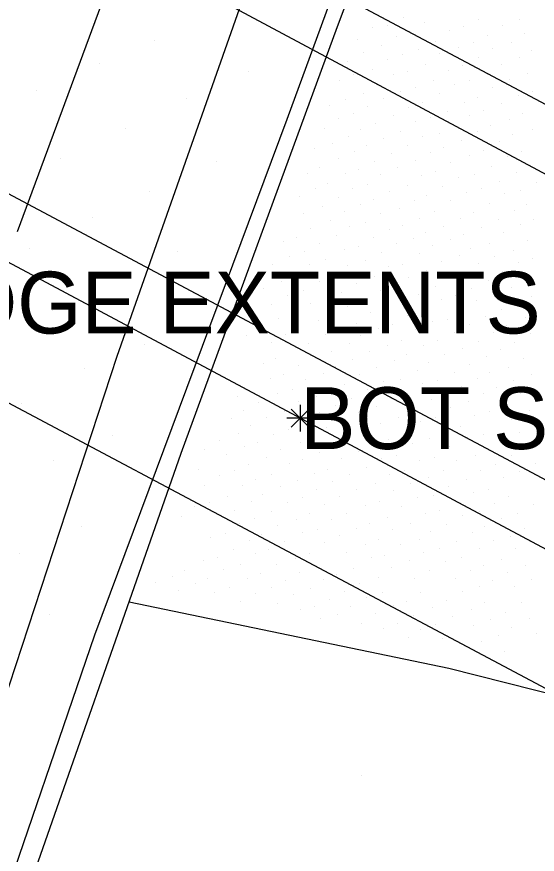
# Model space of a CAD drawing. Extents: x 1729983 to 1730242, y 468641 to 469019.
# Drawn here: x 1730109.61 to 1730124.77, y 468724.33 to 468748.72 of the extents above; entities that cross this region are included whole.
import ezdxf

# ---------------------------------------------------------------- set-up
doc = ezdxf.new("R2010")
doc.units = 0
for name, color, linetype in [('Default', 7, 'Continuous'), ('S_Curb_Type_1', 7, 'Continuous'), ('S_Ground_SpotElevation', 7, 'Continuous'), ('S_Misc_MiscFeature', 7, 'Continuous'), ('S_Misc_MiscItems', 7, 'Continuous'), ('S_Roadway_Edge_Pavement', 7, 'Continuous'), ('S_Roadway_Painted_Lines', 7, 'Continuous'), ('S_Roadway_Sidewalks', 7, 'Continuous'), ('S_Text', 7, 'Continuous')]:
    doc.layers.add(name, color=color, linetype=linetype)

# ---------------------------------------------------------------- blocks, each defined once
blk = doc.blocks.new('POINT_DISPLAY')
at = {"layer": 'Default'}
blk.add_line((0, 0), (0, 0), dxfattribs=at)

msp = doc.modelspace()

# ---------------------------------------------------------------- linework, layer by layer
at = {"layer": 'S_Curb_Type_1'}
msp.add_lwpolyline([(1730095.691, 468641.415), (1730095.909, 468646.136), (1730096.354, 468653.521), (1730096.818, 468653.995), (1730097.198, 468655.848), (1730096.66, 468657.036), (1730097.062, 468660.797), (1730098.243, 468671.757), (1730099.533, 468680.946), (1730101.556, 468692.14), (1730103.524, 468700.629), (1730106.497, 468712.327), (1730109.421, 468721.771), (1730114.404, 468736.003), (1730118.96, 468748.434), (1730124.347, 468762.755), (1730131.22, 468781.92), (1730136.349, 468795.804), (1730142.854, 468813.477), (1730149.849, 468832.496), (1730156.774, 468851.574), (1730163.434, 468869.402), (1730166.697, 468878.04), (1730172.479, 468894.171)], dxfattribs=at)
at = {"layer": 'S_Misc_MiscFeature'}
for p, q in [((1730119.737, 468769.782), (1730109.624, 468742.454)), ((1730134.131, 468741.31), (1730106.222, 468756.158)), ((1730105.571, 468754.535), (1730133.572, 468739.555)), ((1730102.847, 468747.037), (1730130.837, 468732.131)), ((1730130.252, 468730.415), (1730102.19, 468745.399)), ((1730130.021, 468726.489), (1730100.897, 468741.974))]:
    msp.add_line(p, q, dxfattribs=at)
at = {"layer": 'S_Misc_MiscItems'}
for p, q in [((1730118.134, 468736.763), (1730117.61, 468737.287)), ((1730118.134, 468737.287), (1730117.61, 468736.763)), ((1730117.872, 468737.418), (1730117.872, 468736.632)), ((1730118.265, 468737.025), (1730117.479, 468737.025))]:
    msp.add_line(p, q, dxfattribs=at)
at = {"layer": 'S_Roadway_Edge_Pavement'}
msp.add_lwpolyline([(1730169.443, 468886.971), (1730164.503, 468873.715), (1730156.499, 468852.01), (1730147.717, 468828.276), (1730138.371, 468802.607), (1730128.942, 468777.012), (1730117.481, 468745.727), (1730111.874, 468730.709), (1730108.888, 468721.988), (1730105.794, 468711.827), (1730102.94, 468700.647), (1730101.123, 468692.177), (1730099.16, 468681.419), (1730097.818, 468671.805), (1730096.586, 468660.812), (1730096.168, 468657.103), (1730095.956, 468653.708), (1730095.867, 468652.572), (1730095.424, 468646.027), (1730095.252, 468641.367)], dxfattribs=at)
at = {"layer": 'S_Roadway_Painted_Lines'}
msp.add_lwpolyline([(1730094.799, 468656.256), (1730095.17, 468660.96), (1730096.083, 468669.985), (1730097.638, 468680.767), (1730099.581, 468691.95), (1730101.134, 468699.687), (1730104.772, 468714.073), (1730108.651, 468727.01), (1730112.542, 468738.83), (1730119.789, 468759.429), (1730137.203, 468807.807), (1730148.896, 468839.717), (1730160.486, 468871.271), (1730175.799, 468912.851), (1730190.41, 468952.883), (1730200.037, 468978.351)], dxfattribs=at)
at = {"layer": 'S_Roadway_Sidewalks'}
msp.add_lwpolyline([(1730127.192, 468728.47), (1730122.195, 468729.739), (1730112.887, 468731.671)], dxfattribs=at)

# ---------------------------------------------------------------- block references
at = {"layer": 'S_Ground_SpotElevation'}
for p in [(1730120.885, 468748.692), (1730120.425, 468748.456), (1730121.491, 468748.549), (1730123.059, 468748.64), (1730123.749, 468748.457), (1730124.269, 468748.622), (1730119.966, 468748.396), (1730121.041, 468748.291), (1730122.22, 468748.316), (1730122.635, 468748.418), (1730124.412, 468748.23), (1730113.631, 468748.018), (1730119.547, 468748.059), (1730120.686, 468748.132), (1730121.802, 468748.003), (1730122.925, 468747.955), (1730123.33, 468748.178), (1730124.011, 468747.965), (1730120.247, 468747.874), (1730121.304, 468747.768), (1730122.482, 468747.815), (1730123.484, 468747.8), (1730124.608, 468747.73), (1730119.71, 468747.688), (1730120.4, 468747.468), (1730120.854, 468747.612), (1730121.938, 468747.652), (1730123.058, 468747.522), (1730124.25, 468747.515), (1730112.022, 468747.363), (1730119.245, 468747.42), (1730121.517, 468747.33), (1730122.582, 468747.296), (1730123.736, 468747.321), (1730116.352, 468747.126), (1730119.413, 468747.032), (1730119.974, 468747.18), (1730120.576, 468747.028), (1730121.002, 468747.118), (1730122.2, 468747.144), (1730123.317, 468747.027), (1730124.485, 468747.076), (1730119.021, 468746.87), (1730120.131, 468746.767), (1730121.757, 468746.855), (1730122.365, 468746.743), (1730122.808, 468746.858), (1730123.962, 468746.882), (1730110.192, 468746.566), (1730119.71, 468746.489), (1730120.805, 468746.543), (1730121.218, 468746.669), (1730123.479, 468746.648), (1730124.635, 468746.537), (1730114.56, 468746.334), (1730119.178, 468746.303), (1730120.301, 468746.333), (1730121.917, 468746.466), (1730123.031, 468746.367), (1730124.217, 468746.41), (1730118.73, 468746.12), (1730119.834, 468746.11), (1730121.03, 468746.081), (1730121.442, 468746.211), (1730122.648, 468746.21), (1730123.733, 468746.178), (1730119.435, 468745.911), (1730120.574, 468745.832), (1730121.65, 468745.77), (1730122.171, 468745.966), (1730122.794, 468745.841), (1730123.194, 468745.989), (1730124.357, 468745.896), (1730118.986, 468745.753), (1730120.063, 468745.621), (1730121.229, 468745.656), (1730122.333, 468745.576), (1730123.42, 468745.554), (1730123.978, 468745.728), (1730112.782, 468745.464), (1730118.587, 468745.467), (1730119.611, 468745.427), (1730120.802, 468745.362), (1730121.917, 468745.327), (1730123.036, 468745.381), (1730124.048, 468745.273), (1730124.647, 468745.446), (1730119.267, 468745.223), (1730120.305, 468745.166), (1730121.439, 468745.225), (1730122.57, 468745.11), (1730123.68, 468745.079), (1730118.283, 468744.88), (1730118.817, 468745.015), (1730119.465, 468744.785), (1730119.809, 468744.97), (1730120.995, 468744.953), (1730122.047, 468744.913), (1730123.206, 468744.814), (1730124.32, 468744.784), (1730110.88, 468744.576), (1730118.997, 468744.6), (1730120.518, 468744.724), (1730121.222, 468744.543), (1730121.677, 468744.755), (1730122.8, 468744.666), (1730123.918, 468744.633), (1730115.439, 468744.51), (1730118.43, 468744.325), (1730120.027, 468744.51), (1730120.696, 468744.339), (1730122.259, 468744.479), (1730123.455, 468744.357), (1730124.491, 468744.397), (1730118.095, 468744.162), (1730119.201, 468744.143), (1730119.562, 468744.281), (1730120.219, 468744.111), (1730121.391, 468744.078), (1730121.805, 468744.22), (1730122.937, 468744.131), (1730124.168, 468744.168), (1730118.65, 468743.868), (1730119.821, 468743.835), (1730120.994, 468743.811), (1730122.489, 468744.031), (1730123.677, 468743.932), (1730124.739, 468743.901), (1730113.481, 468743.638), (1730118.317, 468743.712), (1730119.4, 468743.702), (1730120.481, 468743.633), (1730122.02, 468743.783), (1730122.71, 468743.605), (1730123.151, 468743.715), (1730123.826, 468743.572), (1730124.288, 468743.642), (1730117.849, 468743.494), (1730118.987, 468743.438), (1730120.003, 468743.382), (1730121.206, 468743.375), (1730121.552, 468743.524), (1730122.233, 468743.355), (1730118.518, 468743.189), (1730119.638, 468743.25), (1730120.769, 468743.126), (1730123.374, 468743.283), (1730124.466, 468743.245), (1730111.818, 468742.883), (1730117.966, 468742.996), (1730119.148, 468743.058), (1730120.218, 468742.991), (1730121.331, 468742.844), (1730121.767, 468743.057), (1730122.532, 468742.849), (1730122.918, 468743.008), (1730124.101, 468743.063), (1730118.753, 468742.77), (1730119.297, 468742.594), (1730119.767, 468742.737), (1730120.859, 468742.642), (1730122.053, 468742.604), (1730123.631, 468742.805), (1730124.281, 468742.652), (1730124.66, 468742.818), (1730118.173, 468742.557), (1730118.929, 468742.354), (1730120.483, 468742.511), (1730121.519, 468742.443), (1730122.629, 468742.373), (1730123.141, 468742.576), (1730123.798, 468742.418), (1730117.372, 468742.16), (1730117.767, 468742.291), (1730118.429, 468742.12), (1730119.996, 468742.3), (1730120.671, 468742.105), (1730121.183, 468742.263), (1730122.233, 468742.238), (1730123.381, 468742.121), (1730124.481, 468742.212), (1730109.989, 468741.962), (1730114.295, 468741.886), (1730118.005, 468741.867), (1730119.147, 468741.924), (1730119.56, 468742.035), (1730121.716, 468742.046), (1730122.834, 468741.971), (1730124.075, 468741.904), (1730117.556, 468741.747), (1730118.592, 468741.634), (1730119.778, 468741.612), (1730120.249, 468741.836), (1730121.334, 468741.814), (1730122.521, 468741.75), (1730123.534, 468741.745), (1730124.623, 468741.689), (1730117.069, 468741.5), (1730118.132, 468741.508), (1730119.245, 468741.463), (1730120.431, 468741.43), (1730120.853, 468741.51), (1730121.993, 468741.577), (1730123.076, 468741.515), (1730124.223, 468741.547), (1730112.474, 468741.147), (1730117.771, 468741.28), (1730118.835, 468741.146), (1730120.028, 468741.139), (1730121.024, 468741.131), (1730121.538, 468741.313), (1730122.175, 468741.168), (1730122.628, 468741.261), (1730123.768, 468741.302), (1730117.321, 468741.016), (1730118.432, 468741.017), (1730119.513, 468740.948), (1730120.558, 468740.904), (1730123.341, 468741.021), (1730124.455, 468740.972), (1730116.808, 468740.793), (1730117.969, 468740.744), (1730119.061, 468740.689), (1730120.198, 468740.744), (1730121.304, 468740.638), (1730121.801, 468740.853), (1730122.87, 468740.803), (1730123.486, 468740.66), (1730124.02, 468740.832), (1730117.506, 468740.596), (1730119.762, 468740.47), (1730120.839, 468740.391), (1730121.982, 468740.475), (1730122.38, 468740.594), (1730123.014, 468740.447), (1730124.61, 468740.567), (1730110.657, 468740.17), (1730117.039, 468740.344), (1730118.164, 468740.359), (1730119.256, 468740.279), (1730120.318, 468740.212), (1730121.549, 468740.204), (1730122.586, 468740.185), (1730123.745, 468740.184), (1730124.17, 468740.293), (1730117.228, 468739.927), (1730117.723, 468740.117), (1730118.807, 468740.024), (1730119.913, 468740.098), (1730121.005, 468740.018), (1730122.156, 468739.912), (1730123.259, 468739.975), (1730124.437, 468739.957), (1730118.392, 468739.881), (1730119.504, 468739.793), (1730120.56, 468739.749), (1730121.716, 468739.833), (1730122.81, 468739.745), (1730123.891, 468739.713), (1730116.296, 468739.431), (1730116.768, 468739.658), (1730117.438, 468739.457), (1730118.592, 468739.452), (1730119.017, 468739.579), (1730119.638, 468739.436), (1730120.153, 468739.629), (1730121.232, 468739.595), (1730122.352, 468739.511), (1730123.5, 468739.521), (1730124.57, 468739.478), (1730117.023, 468739.243), (1730118.117, 468739.197), (1730119.297, 468739.207), (1730120.81, 468739.286), (1730121.857, 468739.298), (1730123.054, 468739.268), (1730124.113, 468739.228), (1730113.344, 468739.168), (1730118.791, 468738.963), (1730119.879, 468738.957), (1730120.409, 468739.14), (1730121.473, 468739.153), (1730122.584, 468739.048), (1730123.708, 468739.026), (1730117.164, 468738.775), (1730118.304, 468738.788), (1730119.39, 468738.736), (1730120.628, 468738.71), (1730120.97, 468738.88), (1730122.06, 468738.878), (1730123.294, 468738.811), (1730124.361, 468738.766), (1730111.588, 468738.464), (1730116.797, 468738.63), (1730117.814, 468738.57), (1730118.908, 468738.525), (1730120.102, 468738.508), (1730121.596, 468738.638), (1730122.805, 468738.598), (1730123.926, 468738.501), (1730117.395, 468738.296), (1730118.552, 468738.338), (1730119.588, 468738.287), (1730121.275, 468738.411), (1730122.362, 468738.344), (1730123.373, 468738.35), (1730124.614, 468738.306), (1730117.004, 468738.188), (1730118.031, 468738.165), (1730119.171, 468738.019), (1730120.307, 468738.089), (1730120.786, 468738.162), (1730121.43, 468738.047), (1730121.873, 468738.135), (1730123.019, 468738.167), (1730124.096, 468738.119), (1730117.209, 468737.736), (1730117.654, 468737.866), (1730118.802, 468737.881), (1730119.815, 468737.862), (1730120.988, 468737.755), (1730122.067, 468737.713), (1730122.554, 468737.933), (1730123.207, 468737.732), (1730123.592, 468737.921), (1730124.288, 468737.732), (1730116.042, 468737.652), (1730116.653, 468737.469), (1730117.823, 468737.509), (1730118.352, 468737.646), (1730119.373, 468737.599), (1730120.511, 468737.603), (1730121.682, 468737.575), (1730122.762, 468737.504), (1730109.763, 468737.462), (1730116.212, 468737.255), (1730118.9, 468737.391), (1730120.09, 468737.378), (1730121.236, 468737.285), (1730122.239, 468737.327), (1730123.909, 468737.398), (1730124.542, 468737.252), (1730115.859, 468737.003), (1730116.897, 468737.04), (1730117.423, 468737.217), (1730118.437, 468737.18), (1730119.563, 468737.201), (1730120.737, 468737.053), (1730121.796, 468737.045), (1730122.945, 468737.112), (1730123.372, 468737.218), (1730124.034, 468736.982), (1730116.409, 468736.819), (1730118.002, 468736.941), (1730118.644, 468736.751), (1730119.102, 468736.971), (1730120.204, 468736.872), (1730121.366, 468736.942), (1730122.548, 468736.779), (1730112.399, 468736.518), (1730116.081, 468736.589), (1730117.098, 468736.564), (1730117.534, 468736.708), (1730119.329, 468736.51), (1730119.869, 468736.666), (1730120.967, 468736.603), (1730122.052, 468736.606), (1730123.208, 468736.562), (1730124.256, 468736.615), (1730115.531, 468736.382), (1730116.618, 468736.321), (1730117.865, 468736.309), (1730118.274, 468736.473), (1730120.437, 468736.416), (1730121.154, 468736.275), (1730121.639, 468736.437), (1730122.697, 468736.432), (1730123.861, 468736.387), (1730115.077, 468736.125), (1730116.253, 468736.197), (1730117.284, 468736.102), (1730118.426, 468736.013), (1730118.917, 468736.218), (1730119.558, 468736.049), (1730120.054, 468736.24), (1730122.208, 468736.199), (1730123.351, 468736.103), (1730124.494, 468736.165), (1730110.691, 468735.789), (1730115.717, 468735.969), (1730116.881, 468735.87), (1730117.932, 468735.825), (1730119.067, 468735.84), (1730120.236, 468735.855), (1730120.676, 468735.951), (1730121.351, 468735.778), (1730121.786, 468735.892), (1730122.428, 468735.782), (1730122.977, 468735.936), (1730124.011, 468735.925), (1730114.919, 468735.522), (1730116.37, 468735.664), (1730117.557, 468735.693), (1730118.659, 468735.541), (1730119.798, 468735.585), (1730123.55, 468735.688), (1730124.734, 468735.704), (1730115.515, 468735.349), (1730115.968, 468735.496), (1730117.043, 468735.389), (1730118.274, 468735.417), (1730119.303, 468735.37), (1730120.474, 468735.394), (1730120.903, 468735.501), (1730121.599, 468735.31), (1730122.051, 468735.489), (1730123.113, 468735.511), (1730123.802, 468735.297), (1730124.243, 468735.468), (1730115.095, 468735.073), (1730116.192, 468735.064), (1730116.568, 468735.236), (1730117.283, 468735.025), (1730117.795, 468735.206), (1730118.799, 468735.181), (1730120.05, 468735.11), (1730121.085, 468735.116), (1730122.193, 468735.042), (1730122.727, 468735.248), (1730116.767, 468734.806), (1730118.338, 468734.952), (1730119.52, 468734.944), (1730120.579, 468734.907), (1730122.905, 468734.852), (1730123.343, 468734.953), (1730115.215, 468734.569), (1730115.741, 468734.756), (1730116.447, 468734.585), (1730117.504, 468734.568), (1730117.95, 468734.703), (1730119.023, 468734.737), (1730120.175, 468734.598), (1730121.277, 468734.702), (1730121.744, 468734.769), (1730122.456, 468734.565), (1730123.528, 468734.54), (1730123.943, 468734.73), (1730114.788, 468734.454), (1730115.962, 468734.327), (1730117.041, 468734.307), (1730118.565, 468734.501), (1730119.765, 468734.475), (1730120.826, 468734.442), (1730121.921, 468734.348), (1730123.091, 468734.294), (1730124.659, 468734.501), (1730114.424, 468734.175), (1730115.491, 468734.22), (1730116.527, 468734.1), (1730117.752, 468734.077), (1730118.132, 468734.236), (1730118.774, 468734.078), (1730119.214, 468734.261), (1730120.408, 468734.145), (1730121.522, 468734.24), (1730122.606, 468734.2), (1730123.73, 468734.112), (1730124.199, 468734.263), (1730111.513, 468733.872), (1730116.114, 468733.972), (1730117.221, 468733.907), (1730119.516, 468733.813), (1730119.887, 468733.97), (1730121.089, 468733.956), (1730122.14, 468733.94), (1730123.251, 468733.866), (1730124.396, 468733.807), (1730115.682, 468733.66), (1730116.747, 468733.648), (1730117.942, 468733.691), (1730118.361, 468733.774), (1730119.011, 468733.619), (1730120.553, 468733.792), (1730121.653, 468733.721), (1730122.896, 468733.682), (1730123.991, 468733.575), (1730115.263, 468733.541), (1730116.384, 468733.466), (1730117.398, 468733.434), (1730118.578, 468733.408), (1730119.76, 468733.359), (1730120.138, 468733.495), (1730120.795, 468733.341), (1730121.341, 468733.492), (1730122.424, 468733.43), (1730123.513, 468733.461), (1730124.586, 468733.47), (1730109.704, 468733.086), (1730115.923, 468733.204), (1730116.556, 468733.074), (1730116.96, 468733.195), (1730118.143, 468733.094), (1730119.221, 468733.114), (1730121.473, 468733.109), (1730121.93, 468733.228), (1730123.09, 468733.233), (1730124.13, 468733.222), (1730115.052, 468732.866), (1730115.47, 468732.978), (1730117.741, 468732.924), (1730119.933, 468732.959), (1730120.334, 468733.03), (1730121.043, 468732.879), (1730122.095, 468732.848), (1730122.556, 468732.972), (1730123.743, 468732.92), (1730114.499, 468732.6), (1730115.624, 468732.614), (1730116.138, 468732.76), (1730117.173, 468732.775), (1730118.275, 468732.755), (1730119.413, 468732.652), (1730120.54, 468732.683), (1730121.642, 468732.6), (1730122.836, 468732.6), (1730123.218, 468732.743), (1730124.427, 468732.727), (1730114.146, 468732.419), (1730115.175, 468732.346), (1730116.34, 468732.343), (1730116.715, 468732.501), (1730117.841, 468732.527), (1730118.925, 468732.476), (1730120.138, 468732.375), (1730121.189, 468732.356), (1730122.382, 468732.343), (1730123.906, 468732.542), (1730113.65, 468732.225), (1730114.812, 468732.2), (1730117.448, 468732.286), (1730118.558, 468732.315), (1730119.593, 468732.206), (1730123.095, 468732.137), (1730123.46, 468732.311), (1730124.103, 468732.117), (1730124.607, 468732.328), (1730114.339, 468732.011), (1730115.385, 468731.943), (1730115.807, 468732.083), (1730116.569, 468731.918), (1730117.023, 468732.082), (1730117.68, 468731.887), (1730118.158, 468732.057), (1730119.172, 468731.973), (1730120.269, 468731.945), (1730121.381, 468731.95), (1730122.584, 468731.973), (1730116.134, 468731.673), (1730117.196, 468731.623), (1730118.713, 468731.75), (1730119.807, 468731.803), (1730120.953, 468731.689), (1730122.13, 468731.721), (1730123.224, 468731.658), (1730124.311, 468731.67), (1730117.88, 468731.449), (1730118.29, 468731.552), (1730119.344, 468731.548), (1730120.58, 468731.568), (1730121.715, 468731.499), (1730122.849, 468731.44), (1730123.848, 468731.369), (1730110.555, 468731.294), (1730118.456, 468731.201), (1730118.969, 468731.307), (1730120.057, 468731.326), (1730121.171, 468731.274), (1730122.292, 468731.261), (1730123.409, 468731.175), (1730124.538, 468731.203), (1730119.651, 468731.043), (1730120.288, 468730.887), (1730120.7, 468731.036), (1730121.387, 468730.88), (1730121.812, 468731.014), (1730122.915, 468730.981), (1730124.038, 468730.921), (1730121.026, 468730.652), (1730123.639, 468730.709), (1730124.761, 468730.749), (1730122.024, 468730.622), (1730123.139, 468730.515), (1730122.791, 468730.354), (1730123.826, 468730.238), (1730119.655, 468726.605)]:
    msp.add_blockref('POINT_DISPLAY', p, dxfattribs=at)

# ---------------------------------------------------------------- texts
at = {"layer": 'S_Text'}
for s, p in [('BRIDGE EXTENTS', (1730103.875, 468739.491)), ('BOT STEEL GIRDER', (1730117.872, 468736.125))]:
    msp.add_text(s, height=1.8, dxfattribs=at).set_placement(p)

doc.saveas('drawing.dxf')
